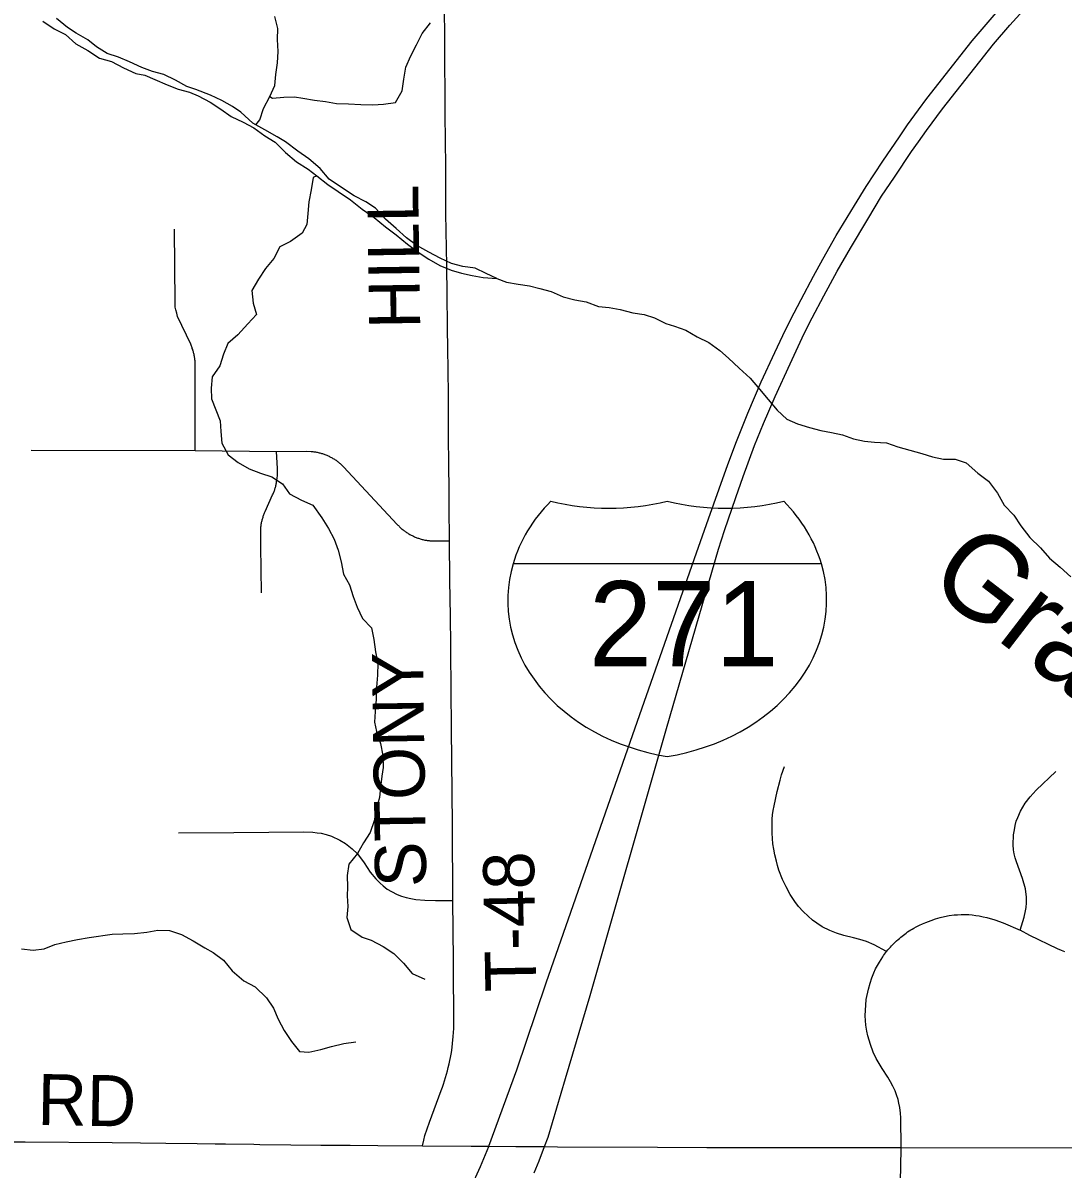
# Model space of a CAD drawing. Extents: x 0 to 34, y 0 to 22.
# Drawn here: x 3.395 to 4.553, y 16.757 to 18.033 of the extents above; entities that cross this region are included whole.
import ezdxf

# ---------------------------------------------------------------- set-up
doc = ezdxf.new("R2010")
doc.units = 0
for name, color, linetype in [('GM_X_County_Road', 7, 'Continuous'), ('GM_X_County_Road_Text', 7, 'Continuous'), ('GM_X_Interstate_Route', 7, 'Continuous'), ('GM_X_Interstate_Shield', 7, 'Continuous'), ('GM_X_Minor_River', 7, 'Continuous'), ('GM_X_Minor_River_Text', 7, 'Continuous'), ('GM_X_Township_Road', 7, 'Continuous'), ('GM_X_Township_Road_Text', 7, 'Continuous')]:
    doc.layers.add(name, color=color, linetype=linetype)

msp = doc.modelspace()

# ---------------------------------------------------------------- linework, layer by layer
at = {"layer": 'GM_X_County_Road'}
for points in [[(3.351, 16.7874), (3.397, 16.7875), (3.494, 16.7869), (3.5254, 16.7864), (3.5536, 16.7861), (3.5885, 16.7856), (3.6088, 16.7853), (3.62, 16.7852), (3.6516, 16.7848), (3.6583, 16.7847), (3.6927, 16.7842), (3.7262, 16.784), (3.7589, 16.7837), (3.7897, 16.7833), (3.8393, 16.7831)], [(3.8393, 16.7831), (3.8937, 16.7827), (3.9134, 16.7826), (3.9434, 16.7824), (3.9752, 16.7822), (3.9899, 16.782), (4.101, 16.7816)], [(4.101, 16.7816), (4.156, 16.7814), (4.3724, 16.7813), (4.6279, 16.781), (4.7265, 16.7807), (4.7711, 16.7805), (4.8188, 16.7803), (4.8961, 16.78), (4.9533, 16.7796), (5.0708, 16.7794), (5.094, 16.7795)]]:
    msp.add_lwpolyline(points, dxfattribs=at)
at = {"layer": 'GM_X_Interstate_Route'}
for points in [[(3.9637, 16.7532), (3.9692, 16.7664), (3.9752, 16.7822), (3.9792, 16.7929), (3.9987, 16.8579), (4.0262, 16.9503), (4.111, 17.2475), (4.169, 17.4472), (4.1757, 17.468), (4.1881, 17.5048), (4.1963, 17.528), (4.2091, 17.5626), (4.2192, 17.5871), (4.232, 17.617), (4.2487, 17.6534), (4.2578, 17.6728), (4.2645, 17.687), (4.2734, 17.7044), (4.2862, 17.7289), (4.3011, 17.7565), (4.3159, 17.7821), (4.3351, 17.8145), (4.3506, 17.8398), (4.365, 17.8613), (4.3839, 17.8897), (4.3917, 17.9006), (4.4006, 17.9131), (4.4182, 17.9371), (4.475, 18.009), (4.4933, 18.0302), (4.5408, 18.0828)], [(3.8931, 16.7364), (3.904, 16.7599), (3.9133, 16.7822), (3.9134, 16.7826), (3.9443, 16.8678), (3.9772, 16.9646), (4.0763, 17.2482), (4.1443, 17.4429), (4.1578, 17.481), (4.1698, 17.5141), (4.1795, 17.5414), (4.1889, 17.5669), (4.2017, 17.5984), (4.2166, 17.6332), (4.2318, 17.6661), (4.2407, 17.6849), (4.2492, 17.7024), (4.2609, 17.7249), (4.2746, 17.7508), (4.285, 17.7699), (4.3, 17.7961), (4.3205, 17.8294), (4.3335, 17.8507), (4.3518, 17.8791), (4.3705, 17.906), (4.3795, 17.9192), (4.3917, 17.936), (4.4008, 17.9487), (4.4514, 18.0128), (4.478, 18.0439)]]:
    msp.add_lwpolyline(points, dxfattribs=at)
at = {"layer": 'GM_X_Interstate_Shield'}
msp.add_line((4.2836, 17.4309), (3.9402, 17.4309), dxfattribs=at)
msp.add_line((4.2836, 17.4309), (3.9402, 17.4309), dxfattribs=at)
for centre, start_param, end_param in [((4.1563, 17.3903), 2.47259, 2.911027), ((4.047, 17.6702), 4.415841, 5.008937), ((4.1767, 17.6702), 4.415841, 5.008937), ((4.0675, 17.3903), 0.230566, 0.669003), ((4.1563, 17.3903), 2.911027, 4.511031), ((4.0675, 17.3903), 4.913747, 6.513751)]:
    msp.add_ellipse(centre, major_axis=(0.2219, 0), ratio=0.8, start_param=start_param, end_param=end_param, dxfattribs=at)
at = {"layer": 'GM_X_Minor_River'}
for points in [[(3.5771, 17.962), (3.5644, 17.969), (3.5515, 17.9753), (3.5389, 17.9788), (3.5271, 17.9832), (3.5134, 17.9894), (3.5012, 17.9945), (3.4886, 17.9988), (3.4764, 18.0062), (3.4668, 18.014), (3.4538, 18.0213), (3.4443, 18.0276), (3.432, 18.0377)], [(3.6541, 17.9192), (3.6583, 17.9248), (3.6626, 17.9377), (3.6695, 17.9508), (3.675, 17.963), (3.6763, 17.9755), (3.678, 17.9885), (3.6789, 18.001), (3.6779, 18.0143), (3.6784, 18.0264), (3.6752, 18.04)], [(3.4169, 18.0347), (3.4295, 18.0262), (3.4421, 18.02), (3.4537, 18.0096), (3.467, 18.0022), (3.48, 17.9937), (3.4933, 17.9898), (3.5067, 17.9828), (3.5204, 17.9766), (3.5303, 17.9745), (3.5414, 17.9698), (3.5551, 17.9639), (3.5676, 17.9592), (3.5802, 17.9556), (3.5897, 17.9516), (3.6031, 17.9447), (3.6149, 17.9369), (3.6264, 17.9288)], [(3.6695, 17.9508), (3.6726, 17.9489), (3.6851, 17.9503), (3.6968, 17.9505), (3.7063, 17.9491), (3.7192, 17.9467), (3.7313, 17.9454), (3.7438, 17.943), (3.7571, 17.9428), (3.7707, 17.9419), (3.7843, 17.9418), (3.796, 17.9424), (3.8093, 17.9441), (3.817, 17.9571), (3.8186, 17.9701), (3.821, 17.9834), (3.8265, 17.996), (3.8327, 18.0083), (3.8389, 18.0209), (3.8485, 18.0328)], [(3.9223, 17.7484), (3.9102, 17.7539), (3.898, 17.7598), (3.8843, 17.7618), (3.8718, 17.765), (3.8592, 17.7709), (3.8466, 17.7778), (3.8332, 17.7852), (3.8217, 17.7937), (3.8102, 17.8041), (3.7983, 17.8142), (3.7871, 17.8265), (3.7764, 17.8335), (3.7634, 17.8405), (3.7493, 17.8497), (3.7355, 17.859), (3.7254, 17.8709), (3.7128, 17.8817), (3.7005, 17.8902), (3.6871, 17.9006), (3.6775, 17.9061), (3.6638, 17.9139), (3.6504, 17.9212), (3.6373, 17.9335), (3.6278, 17.9398), (3.6159, 17.9464), (3.6033, 17.9523), (3.5873, 17.9588), (3.5771, 17.962)], [(3.6264, 17.9288), (3.6398, 17.9222), (3.6516, 17.9159), (3.6639, 17.907), (3.6754, 17.9), (3.6869, 17.8885), (3.6992, 17.8781), (3.7122, 17.8699), (3.7218, 17.8625), (3.7341, 17.8529), (3.7456, 17.8451), (3.7593, 17.8359), (3.7724, 17.8255), (3.7858, 17.8162), (3.7981, 17.8058), (3.81, 17.7969), (3.8226, 17.7865), (3.8345, 17.7776), (3.8464, 17.7699), (3.8586, 17.7629), (3.8712, 17.7578), (3.883, 17.7542), (3.8947, 17.7517), (3.9069, 17.7493), (3.9223, 17.7484)], [(3.7218, 17.8625), (3.7177, 17.8606), (3.7156, 17.8469), (3.7129, 17.8335), (3.7119, 17.8206), (3.7106, 17.8085), (3.7055, 17.7989), (3.6924, 17.7896), (3.6808, 17.7837), (3.6739, 17.7706), (3.6646, 17.7595), (3.6569, 17.7476), (3.6495, 17.7349), (3.6509, 17.7209), (3.6545, 17.7081), (3.6449, 17.698), (3.6338, 17.6857), (3.6226, 17.676), (3.6179, 17.6642), (3.6139, 17.6512), (3.6054, 17.6389), (3.6042, 17.6264), (3.6044, 17.6143), (3.6095, 17.6022), (3.6143, 17.5901), (3.6148, 17.578), (3.6162, 17.5651), (3.6232, 17.552), (3.6344, 17.5435), (3.6466, 17.5365), (3.6592, 17.5317), (3.6717, 17.5278), (3.6836, 17.52), (3.6913, 17.5088), (3.7047, 17.5018), (3.7173, 17.496), (3.7274, 17.4821), (3.7348, 17.4701), (3.741, 17.4581), (3.7454, 17.446), (3.749, 17.4332), (3.7515, 17.4192), (3.7582, 17.4075), (3.7622, 17.3943), (3.7669, 17.3826), (3.7728, 17.3698), (3.7825, 17.3594), (3.7854, 17.3465), (3.7871, 17.3329), (3.7896, 17.3201), (3.7895, 17.3068), (3.7882, 17.2935), (3.788, 17.2802), (3.7868, 17.2665), (3.7862, 17.2544), (3.7883, 17.2441), (3.7927, 17.2309), (3.7952, 17.2173), (3.7958, 17.2041), (3.7941, 17.1945), (3.7928, 17.1824), (3.7915, 17.1706), (3.7879, 17.1573), (3.7855, 17.1447), (3.7812, 17.1317), (3.7738, 17.1202), (3.7672, 17.1083), (3.7576, 17.0964), (3.7556, 17.0838), (3.7558, 17.0709), (3.7556, 17.0614), (3.7562, 17.0493), (3.7552, 17.0372), (3.7596, 17.024), (3.7723, 17.0154), (3.7822, 17.0118), (3.7955, 17.0049), (3.8074, 16.9971), (3.8182, 16.9863), (3.8278, 16.9747), (3.8419, 16.9685)], [(3.9223, 17.7484), (3.9331, 17.7441), (3.946, 17.742), (3.9585, 17.74), (3.9699, 17.7371), (3.9828, 17.7339), (3.9961, 17.7281), (4.0091, 17.7245), (4.0216, 17.7225), (4.0353, 17.717), (4.0474, 17.7161), (4.0596, 17.714), (4.0736, 17.7101), (4.0861, 17.7084), (4.0979, 17.7045), (4.1105, 17.6982), (4.12, 17.6954), (4.1326, 17.6907), (4.1452, 17.6833), (4.1582, 17.6771), (4.1704, 17.6682), (4.1801, 17.6596), (4.192, 17.6484), (4.2043, 17.6373), (4.2147, 17.6253), (4.2244, 17.6137), (4.2344, 17.6018), (4.2452, 17.5917), (4.257, 17.5866), (4.2703, 17.5827), (4.2828, 17.5791), (4.2946, 17.577), (4.3071, 17.5742), (4.3193, 17.5699), (4.3315, 17.5674), (4.3428, 17.5661), (4.3561, 17.5656), (4.3687, 17.5609), (4.382, 17.5573), (4.3953, 17.5534), (4.4071, 17.5498), (4.4196, 17.5473), (4.4324, 17.5472), (4.4446, 17.5432), (4.4577, 17.5317), (4.4696, 17.5228), (4.4796, 17.5093), (4.4871, 17.4962), (4.4978, 17.485), (4.5056, 17.473), (4.5157, 17.4602), (4.5276, 17.4487), (4.5373, 17.4371), (4.5492, 17.4271), (4.5611, 17.4163)], [(3.3931, 17.0024), (3.406, 17.0007), (3.4181, 17.0024), (3.4301, 17.0072), (3.4429, 17.0101), (3.4553, 17.0126), (3.4682, 17.0151), (3.4938, 17.0185), (3.5059, 17.0191), (3.5188, 17.0194), (3.5324, 17.0207), (3.5448, 17.0232), (3.5577, 17.0227), (3.571, 17.0184), (3.5843, 17.0114), (3.597, 17.0036), (3.6065, 16.9981), (3.618, 16.9896), (3.6277, 16.978), (3.6404, 16.9668), (3.6533, 16.9602), (3.6657, 16.9479), (3.6734, 16.9363), (3.6789, 16.9239), (3.6856, 16.9115), (3.6938, 16.8991), (3.7026, 16.8879), (3.7129, 16.8873), (3.7261, 16.8902), (3.7381, 16.8938), (3.7517, 16.8971), (3.7652, 16.8988)]]:
    msp.add_lwpolyline(points, dxfattribs=at)
at = {"layer": 'GM_X_Township_Road'}
for points in [[(3.8393, 16.7831), (3.8408, 16.7894), (3.8422, 16.7945), (3.8474, 16.8095), (3.8604, 16.8446), (3.8617, 16.8482), (3.863, 16.8518), (3.8641, 16.8555), (3.8652, 16.8592), (3.8663, 16.8629), (3.8673, 16.8666), (3.8682, 16.8704), (3.8691, 16.8742), (3.8698, 16.8779), (3.8706, 16.8814), (3.8713, 16.885), (3.872, 16.8893), (3.873, 16.897), (3.8737, 16.9048), (3.8742, 16.9138), (3.874, 16.9898), (3.8734, 17.0562), (3.873, 17.1404), (3.8717, 17.2477), (3.8714, 17.2906), (3.8705, 17.378), (3.8703, 17.3868), (3.8696, 17.45), (3.8696, 17.4563), (3.8693, 17.4943), (3.869, 17.5195), (3.8688, 17.5348), (3.8685, 17.5793), (3.8683, 17.6159), (3.8679, 17.6493), (3.8676, 17.6677), (3.8673, 17.6956), (3.8671, 17.7298), (3.8665, 17.7627), (3.8656, 17.8208), (3.8654, 17.8764), (3.8651, 17.8985), (3.8648, 17.9342), (3.8642, 18.0093), (3.8638, 18.0565)], [(3.5864, 17.5568), (3.5862, 17.6567), (3.5861, 17.6577), (3.586, 17.6586), (3.5859, 17.6596), (3.5857, 17.6606), (3.5856, 17.6616), (3.5854, 17.6626), (3.5851, 17.6637), (3.5849, 17.6647), (3.5847, 17.6656), (3.5844, 17.6666), (3.5842, 17.6676), (3.5839, 17.6685), (3.5836, 17.6694), (3.5832, 17.6704), (3.5829, 17.6713), (3.5826, 17.6722), (3.5822, 17.6732), (3.5818, 17.6741), (3.5814, 17.6751), (3.5669, 17.7062), (3.5658, 17.7098), (3.5648, 17.7133), (3.5643, 17.7164), (3.564, 17.7213), (3.5634, 17.8032)], [(3.4038, 17.5573), (3.5864, 17.5568), (3.6771, 17.5559), (3.7105, 17.5561), (3.7154, 17.5559), (3.7164, 17.5558), (3.7174, 17.5557), (3.7184, 17.5556), (3.7194, 17.5555), (3.7203, 17.5553), (3.7213, 17.5551), (3.7223, 17.5549), (3.7233, 17.5547), (3.7243, 17.5545), (3.7252, 17.5542), (3.7262, 17.554), (3.7271, 17.5537), (3.7281, 17.5534), (3.729, 17.5531), (3.73, 17.5528), (3.7309, 17.5524), (3.7318, 17.5521), (3.7328, 17.5517), (3.7337, 17.5513), (3.7346, 17.5509), (3.7355, 17.5505), (3.7364, 17.55), (3.7372, 17.5496), (3.7381, 17.5491), (3.739, 17.5486), (3.7398, 17.5481), (3.7407, 17.5476), (3.7415, 17.5471), (3.7424, 17.5465), (3.7432, 17.546), (3.744, 17.5454), (3.7448, 17.5448), (3.7456, 17.5442), (3.7463, 17.5436), (3.7471, 17.543), (3.7479, 17.5423), (3.7486, 17.5417), (3.7493, 17.541), (3.75, 17.5403), (3.7508, 17.5396), (3.7514, 17.5389), (3.8112, 17.4747), (3.8119, 17.474), (3.8126, 17.4733), (3.8133, 17.4726), (3.814, 17.4719), (3.8147, 17.4712), (3.8155, 17.4705), (3.8162, 17.4699), (3.817, 17.4693), (3.8178, 17.4686), (3.8185, 17.468), (3.8193, 17.4674), (3.8201, 17.4668), (3.821, 17.4663), (3.8218, 17.4657), (3.8226, 17.4652), (3.8235, 17.4646), (3.8243, 17.4641), (3.8252, 17.4636), (3.826, 17.4631), (3.8269, 17.4627), (3.8278, 17.4622), (3.8287, 17.4618), (3.8296, 17.4614), (3.8305, 17.461), (3.8314, 17.4606), (3.8323, 17.4602), (3.8333, 17.4598), (3.8342, 17.4595), (3.8351, 17.4592), (3.8361, 17.4588), (3.837, 17.4585), (3.838, 17.4583), (3.8389, 17.458), (3.8399, 17.4578), (3.8409, 17.4575), (3.8419, 17.4573), (3.8428, 17.4571), (3.8438, 17.457), (3.8448, 17.4568), (3.8458, 17.4567), (3.8467, 17.4566), (3.8477, 17.4564), (3.8487, 17.4564), (3.8497, 17.4563), (3.8696, 17.4563)], [(3.6602, 17.3984), (3.6594, 17.4503), (3.6593, 17.465), (3.6594, 17.4701), (3.6595, 17.4711), (3.6596, 17.4721), (3.6597, 17.4731), (3.6599, 17.4741), (3.66, 17.4751), (3.6602, 17.476), (3.6604, 17.477), (3.6606, 17.478), (3.6608, 17.4789), (3.6611, 17.4799), (3.6613, 17.4809), (3.6616, 17.4818), (3.6619, 17.4828), (3.6622, 17.4837), (3.6625, 17.4846), (3.6628, 17.4856), (3.6632, 17.4865), (3.6636, 17.4874), (3.6639, 17.4883), (3.6643, 17.4892), (3.6726, 17.5075), (3.6731, 17.5086), (3.6735, 17.5095), (3.6739, 17.5104), (3.6742, 17.5113), (3.6746, 17.5123), (3.6749, 17.5132), (3.6752, 17.5141), (3.6755, 17.5151), (3.6757, 17.516), (3.676, 17.517), (3.6762, 17.518), (3.6764, 17.5189), (3.6766, 17.5199), (3.6768, 17.5209), (3.677, 17.5219), (3.6771, 17.5228), (3.6773, 17.5238), (3.6774, 17.5248), (3.6776, 17.5259), (3.6779, 17.5296), (3.678, 17.5368), (3.6771, 17.5559)], [(4.356, 16.9994), (4.3424, 17.0069), (4.3336, 17.0104), (4.3262, 17.0127), (4.3191, 17.0146), (4.3084, 17.0172), (4.3004, 17.0198), (4.2929, 17.0228), (4.2845, 17.0268), (4.2784, 17.0308), (4.2737, 17.0342), (4.2687, 17.0385), (4.2633, 17.0438), (4.258, 17.0496), (4.2539, 17.055), (4.2487, 17.0628), (4.2442, 17.0715), (4.2403, 17.0796), (4.2363, 17.0898), (4.2347, 17.095), (4.2334, 17.0999), (4.2317, 17.1071), (4.2305, 17.1133), (4.2296, 17.119), (4.2287, 17.1311), (4.2286, 17.1412), (4.2289, 17.1465), (4.2292, 17.1514), (4.23, 17.1562), (4.2309, 17.1616), (4.2344, 17.1776), (4.2376, 17.1902), (4.2392, 17.1961), (4.2423, 17.2054)], [(4.5048, 17.023), (4.5094, 17.0375), (4.5109, 17.0445), (4.5114, 17.0482), (4.5118, 17.0537), (4.512, 17.0597), (4.5107, 17.0691), (4.5075, 17.0806), (4.504, 17.0898), (4.5006, 17.0992), (4.4992, 17.1036), (4.4981, 17.1079), (4.4973, 17.1124), (4.4969, 17.118), (4.4974, 17.1291), (4.4984, 17.1346), (4.4992, 17.1397), (4.5005, 17.1444), (4.5021, 17.1486), (4.5053, 17.1557), (4.5105, 17.1645), (4.5161, 17.1715), (4.5227, 17.1789), (4.5445, 17.1995)], [(3.5679, 17.1315), (3.6295, 17.1318), (3.7072, 17.1325), (3.7173, 17.1322), (3.7223, 17.1316), (3.7268, 17.1309), (3.7322, 17.1297), (3.7381, 17.1277), (3.7474, 17.1234), (3.7539, 17.1194), (3.761, 17.1137), (3.767, 17.1079), (3.7746, 17.0979), (3.7813, 17.0878), (3.7876, 17.0802), (3.7924, 17.0754), (3.7958, 17.0723), (3.8003, 17.0688), (3.805, 17.066), (3.8112, 17.0627), (3.816, 17.0611), (3.8213, 17.0594), (3.8266, 17.0582), (3.8321, 17.0571), (3.8422, 17.0563), (3.8541, 17.0562), (3.8734, 17.0562)], [(4.3724, 16.7813), (4.372, 16.8141), (4.3715, 16.8196), (4.3708, 16.8258), (4.3699, 16.8305), (4.369, 16.8348), (4.3673, 16.8398), (4.3656, 16.8444), (4.3631, 16.8496), (4.3603, 16.8544), (4.3574, 16.8596), (4.3512, 16.8691), (4.3479, 16.8746), (4.3446, 16.8804), (4.3413, 16.8874), (4.3382, 16.8958), (4.3367, 16.9005), (4.3352, 16.9055), (4.3342, 16.9108), (4.3331, 16.9172), (4.3324, 16.9277), (4.3333, 16.9459), (4.3358, 16.9574), (4.3377, 16.9642), (4.3396, 16.9702), (4.3419, 16.9757), (4.3439, 16.98), (4.3481, 16.9873), (4.3518, 16.9935), (4.3528, 16.995), (4.356, 16.9994), (4.3576, 17.0013), (4.3589, 17.0028), (4.3603, 17.0043), (4.3616, 17.0057), (4.363, 17.0072), (4.3644, 17.0086), (4.3658, 17.0099), (4.3673, 17.0113), (4.3688, 17.0126), (4.3703, 17.0139), (4.3718, 17.0152), (4.3733, 17.0165), (4.3763, 17.0188), (4.3779, 17.0199), (4.3795, 17.0211), (4.3812, 17.0222), (4.3829, 17.0233), (4.3845, 17.0243), (4.3864, 17.0253), (4.3892, 17.0268), (4.3928, 17.0286), (4.3961, 17.0302), (4.3996, 17.0317), (4.4028, 17.0329), (4.4057, 17.034), (4.4106, 17.0357), (4.4157, 17.0371), (4.4205, 17.0384), (4.4258, 17.0393), (4.4315, 17.04), (4.4351, 17.0403), (4.4393, 17.0405), (4.4477, 17.0404), (4.4514, 17.0401), (4.4556, 17.0395), (4.4592, 17.039), (4.4636, 17.0381), (4.4678, 17.0372), (4.4765, 17.0347), (4.4858, 17.0312), (4.5048, 17.023)], [(4.5544, 16.9989), (4.5507, 17.0005), (4.5464, 17.0022), (4.5157, 17.0171), (4.5048, 17.023)], [(4.358, 15.8728), (4.3587, 16.0036), (4.3593, 16.1711), (4.3594, 16.1911), (4.3601, 16.2593), (4.3604, 16.2735), (4.3607, 16.3036), (4.3611, 16.3362), (4.3618, 16.3736), (4.3624, 16.3988), (4.3629, 16.4218), (4.3637, 16.4453), (4.3644, 16.4739), (4.3651, 16.5022), (4.3657, 16.5308), (4.3666, 16.5627), (4.3675, 16.5927), (4.3683, 16.6229), (4.3689, 16.6535), (4.37, 16.6873), (4.3719, 16.7595), (4.3724, 16.7813)]]:
    msp.add_lwpolyline(points, dxfattribs=at)

# ---------------------------------------------------------------- texts
at = {"layer": 'GM_X_County_Road_Text'}
msp.add_text('RD', height=0.05682, rotation=359.0128, dxfattribs=at).set_placement((3.4105, 16.8063))
at = {"layer": 'GM_X_Interstate_Shield'}
msp.add_text('271', height=0.0947, dxfattribs=at).set_placement((4.0247, 17.3169))
at = {"layer": 'GM_X_Minor_River_Text'}
msp.add_text('Granger', height=0.09474, rotation=322.4231, dxfattribs=at).set_placement((4.3986, 17.4079))
at = {"layer": 'GM_X_Township_Road_Text'}
for s, rotation, p in [('HILL', 90.86, (3.837, 17.6927)), ('STONY', 90.8259, (3.8437, 17.0713)), ('T-48', 91.0603, (3.9663, 16.9549))]:
    msp.add_text(s, height=0.05682, rotation=rotation, dxfattribs=at).set_placement(p)

doc.saveas('drawing.dxf')
